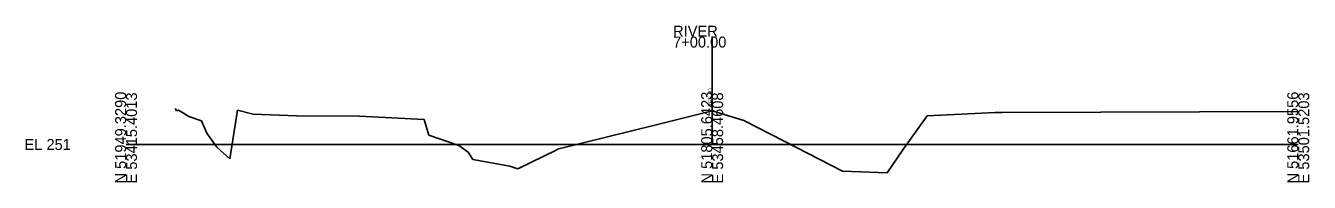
# Model space of a CAD drawing. Extents: x 5628 to 5956, y 92469 to 104012.
# Drawn here: x 5627.6 to 5956.2, y 96468.9 to 96509 of the extents above; entities that cross this region are included whole.
import ezdxf

# ---------------------------------------------------------------- set-up
doc = ezdxf.new("R2010")
doc.units = 0
for name, color, linetype in [('Level 10', 7, 'Continuous'), ('Level 60', 7, 'Continuous'), ('Level 63', 7, 'Continuous')]:
    doc.layers.add(name, color=color, linetype=linetype)

msp = doc.modelspace()

# ---------------------------------------------------------------- linework, layer by layer
at = {"layer": 'Level 60'}
for p, q in [((5665.87, 96487.8), (5666.24, 96487.24)), ((5666.24, 96487.24), (5666.75, 96487.41)), ((5666.75, 96487.41), (5668.01, 96486.58)), ((5668.01, 96486.58), (5669.36, 96485.76)), ((5679.86, 96474.91), (5681.82, 96487.38)), ((5681.82, 96487.38), (5685.85, 96486.39)), ((5788.67, 96483.55), (5803.34, 96487.22)), ((5803.34, 96487.22), (5811.48, 96484.74)), ((5858.33, 96485.92), (5875.77, 96486.78)), ((5875.77, 96486.78), (5876.74, 96486.78)), ((5876.74, 96486.78), (5877.55, 96486.8)), ((5877.55, 96486.8), (5953.34, 96487.08)), ((5669.36, 96485.76), (5672.62, 96484.69)), ((5672.62, 96484.69), (5674, 96481.47)), ((5685.85, 96486.39), (5697, 96485.95)), ((5697, 96485.95), (5713.05, 96485.82)), ((5713.05, 96485.82), (5729.61, 96484.98)), ((5729.61, 96484.98), (5730.84, 96480.96)), ((5763.76, 96477.37), (5788.67, 96483.55)), ((5811.48, 96484.74), (5821.9, 96479.38)), ((5852.17, 96477.21), (5858.33, 96485.92)), ((5674, 96481.47), (5676.58, 96477.87)), ((5730.84, 96480.96), (5738.49, 96478.36)), ((5676.58, 96477.87), (5679.86, 96474.91)), ((5738.49, 96478.36), (5740.93, 96476.63)), ((5753.61, 96472.38), (5763.6, 96477.19)), ((5763.6, 96477.19), (5763.76, 96477.37)), ((5821.9, 96479.38), (5836.69, 96471.8)), ((5848.11, 96471.3), (5852.17, 96477.21)), ((5740.93, 96476.63), (5742.13, 96474.76)), ((5742.13, 96474.76), (5751.53, 96473.06)), ((5751.53, 96473.06), (5753.61, 96472.38)), ((5836.69, 96471.8), (5848.11, 96471.3))]:
    msp.add_line(p, q, dxfattribs=at)
at = {"layer": 'Level 63'}
for p, q in [((5803.34, 96478.6), (5803.34, 96506.22)), ((5653.34, 96478.6), (5803.34, 96478.6)), ((5803.34, 96478.6), (5953.34, 96478.6))]:
    msp.add_line(p, q, dxfattribs=at)

# ---------------------------------------------------------------- texts
at = {"layer": 'Level 10'}
msp.add_text('255.31', height=1.2, rotation=90, dxfattribs=at).set_placement((5803.54, 96488.22))
at = {"layer": 'Level 63'}
for s, p in [('7+00.00', (5793.34, 96503.42)), ('RIVER', (5793.34, 96506.22)), ('EL 251', (5627.34, 96477.2))]:
    msp.add_text(s, height=2.8, dxfattribs=at).set_placement(p)
for s, p in [('N 51949.3290', (5653.34, 96468.6)), ('E 53415.4013', (5656.14, 96468.6)), ('N 51805.6423', (5803.34, 96468.59)), ('E 53458.4608', (5806.14, 96468.6)), ('N 51661.9556', (5953.34, 96468.6)), ('E 53501.5203', (5956.14, 96468.6))]:
    msp.add_text(s, height=2.8, rotation=90, dxfattribs=at).set_placement(p)

doc.saveas('drawing.dxf')
